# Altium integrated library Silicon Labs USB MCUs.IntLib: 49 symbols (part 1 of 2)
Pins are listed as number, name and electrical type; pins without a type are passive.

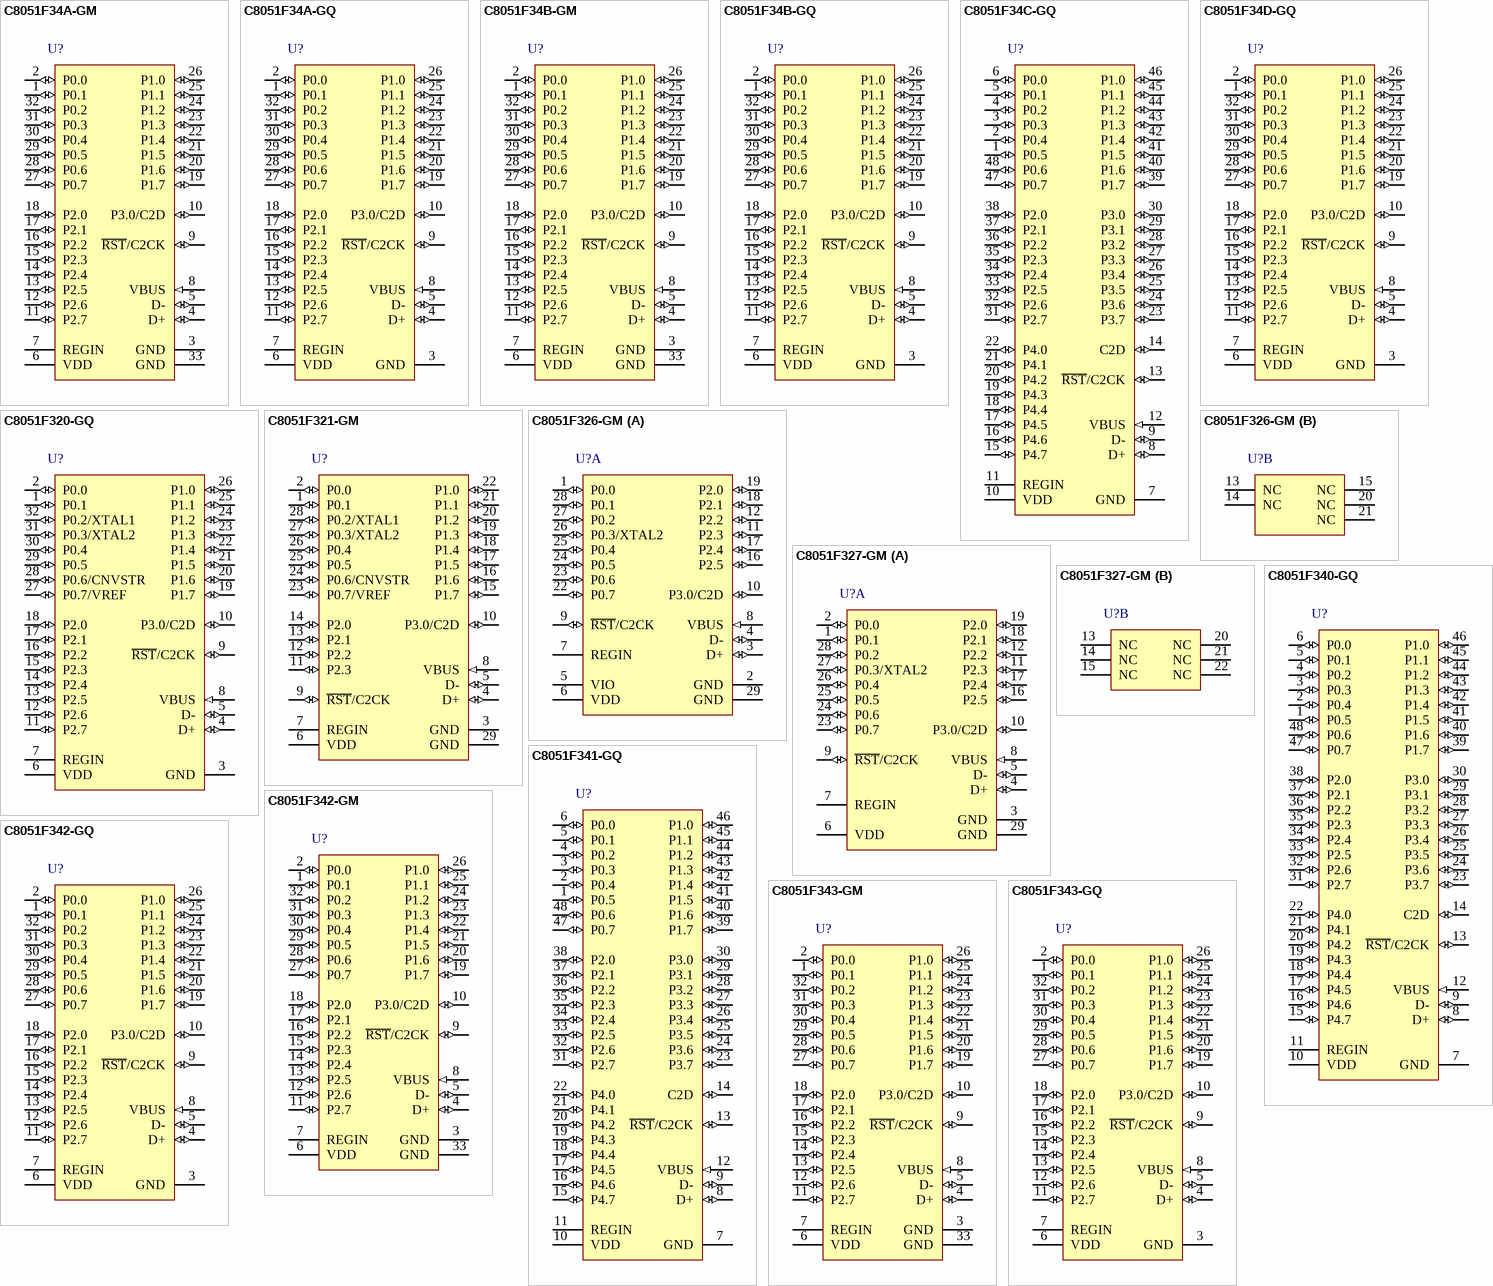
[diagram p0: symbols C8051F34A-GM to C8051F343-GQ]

## C8051F34A-GM
designator U?
Full Speed USB Flash MCU Family, 48 MHz, 4.25 kB RAM, 64 kB Flash, -40 to 85 degC, 32-pin QFN; Manufacturer: Silicon Labs; PartNumber: C8051F34A-GM; AEC-Q100: FALSE; Debug Interface: C2; Dig I/O Pins: 25; Flash: 64 kB; Internal Osc. Accuracy: +/-0.25%; MCU Core: 8051; MHz: 48; PCA Channels: 5; RAM: 4.25 KB; Temp Sensor: TRUE; Timers (16-bit): 4; Sub-Family: USB MCUs
footprint SLAB-QFN-32-3300x3300TP_N (QFN, 32-Leads, Body 5x5mm, Pitch 0.5mm, Thermal Pad 3.3x3.3mm, IPC Medium Density)
footprint SLAB-QFN-32-3300x3300TP_L (QFN, 32-Leads, Body 5x5mm, Pitch 0.5mm, Thermal Pad 3.3x3.3mm, IPC High Density)
footprint SLAB-QFN-32-3300x3300TP_M (QFN, 32-Leads, Body 5x5mm, Pitch 0.5mm, Thermal Pad 3.3x3.3mm, IPC Low Density)
pins: 1 P0.1 (io) "Port 0.1.", 2 P0.0 (io) "Port 0.0.", 3 GND (power) "Ground.", 4 D+ (io) "USB D+.", 5 D- (io) "USB D-", 6 VDD (power) "2.7-3.6 V Power Supply Voltage Input. 3.3 V Voltage Regulator Output.", 7 REGIN (power) "5 V Regulator Input. This pin is the input to the on-chip  voltage regulator.", 8 VBUS (in) "VBUS Sense Input. This pin should be connected to the VBUS signal of a USB network. A 5 V signal on this pin indicates a USB network connection.", 9 ~{RST}/C2CK (io), 10 P3.0/C2D (io), 11 P2.7 (io) "Port 2.7.", 12 P2.6 (io) "Port 2.6.", 13 P2.5 (io) "Port 2.5.", 14 P2.4 (io) "Port 2.4.", 15 P2.3 (io) "Port 2.3.", 16 P2.2 (io) "Port 2.2.", 17 P2.1 (io) "Port 2.1.", 18 P2.0 (io) "Port 2.0.", 19 P1.7 (io) "Port 1.7.", 20 P1.6 (io) "Port 1.6.", 21 P1.5 (io) "Port 1.5.", 22 P1.4 (io) "Port 1.4.", 23 P1.3 (io) "Port 1.3.", 24 P1.2 (io) "Port 1.2.", 25 P1.1 (io) "Port 1.1.", 26 P1.0 (io) "Port 1.0.", 27 P0.7 (io) "Port 0.7.", 28 P0.6 (io) "Port 0.6.", 29 P0.5 (io) "Port 0.5.", 30 P0.4 (io) "Port 0.4.", 31 P0.3 (io) "Port 0.3.", 32 P0.2 (io) "Port 0.2.", 33 GND (power)

## C8051F34A-GQ
designator U?
Full Speed USB Flash MCU Family, 48 MHz, 4.25 kB RAM, 64 kB Flash, -40 to 85 degC, 32-pin QFP; Manufacturer: Silicon Labs; PartNumber: C8051F34A-GQ; AEC-Q100: FALSE; Debug Interface: C2; Dig I/O Pins: 25; Flash: 64 kB; Internal Osc. Accuracy: +/-0.25%; MCU Core: 8051; MHz: 48; PCA Channels: 5; RAM: 4.25 KB; Temp Sensor: TRUE; Timers (16-bit): 4; Sub-Family: USB MCUs
footprint SLAB-LQFP-32_N (QFP, 32-Leads, Body 7x7mm, Pitch 0.8mm, IPC Medium Density)
footprint SLAB-LQFP-32_L (QFP, 32-Leads, Body 7x7mm, Pitch 0.8mm, IPC High Density)
footprint SLAB-LQFP-32_M (QFP, 32-Leads, Body 7x7mm, Pitch 0.8mm, IPC Low Density)
pins: 1 P0.1 (io) "Port 0.1", 2 P0.0 (io) "Port 0.0. See Section 15 for a complete description of Port 0", 3 GND (power) "Ground.", 4 D+ (io) "USB D+.", 5 D- (io) "USB D-.", 6 VDD (power) "2.7-3.6 V Power Supply Voltage Input. 3.3 V Voltage Regulator Output. See Section 8.", 7 REGIN (power) "5 V Regulator Input. This pin is the input to the on-chip voltage regulator.", 8 VBUS (in) "VBUS Sense Input. This pin should be connected to the VBUS signal of a USB network. A 5 V signal on this pin indicates a USB network connection.", 9 ~{RST}/C2CK (io), 10 P3.0/C2D (io), 11 P2.7 (io) "Port 2.7.", 12 P2.6 (io) "Port 2.6.", 13 P2.5 (io) "Port 2.5.", 14 P2.4 (io) "Port 2.4.", 15 P2.3 (io) "Port 2.3.", 16 P2.2 (io) "Port 2.2.", 17 P2.1 (io) "Port 2.1.", 18 P2.0 (io) "Port 2.0. See Section 15 for a complete description of Port 2.", 19 P1.7 (io) "Port 1.7.", 20 P1.6 (io) "Port 1.6.", 21 P1.5 (io) "Port 1.5.", 22 P1.4 (io) "Port 1.4.", 23 P1.3 (io) "Port 1.3.", 24 P1.2 (io) "Port 1.2.", 25 P1.1 (io) "Port 1.1.", 26 P1.0 (io) "Port 1.0. See Section 15 for a complete description of Port 3.", 27 P0.7 (io) "Port 0.7", 28 P0.6 (io) "Port 0.6", 29 P0.5 (io) "Port 0.5", 30 P0.4 (io) "Port 0.4", 31 P0.3 (io) "Port 0.3", 32 P0.2 (io) "Port 0.2"

## C8051F34B-GM
designator U?
Full Speed USB Flash MCU Family, 48 MHz, 2.25 kB RAM, 32 kB Flash, -40 to 85 degC, 32-pin QFN; Manufacturer: Silicon Labs; PartNumber: C8051F34B-GM; AEC-Q100: FALSE; Debug Interface: C2; Dig I/O Pins: 25; Flash: 32 kB; Internal Osc. Accuracy: +/-0.25%; MCU Core: 8051; MHz: 48; PCA Channels: 5; RAM: 2.25 KB; Temp Sensor: TRUE; Timers (16-bit): 4; Sub-Family: USB MCUs
footprint SLAB-QFN-32-3300x3300TP_N (QFN, 32-Leads, Body 5x5mm, Pitch 0.5mm, Thermal Pad 3.3x3.3mm, IPC Medium Density)
footprint SLAB-QFN-32-3300x3300TP_L (QFN, 32-Leads, Body 5x5mm, Pitch 0.5mm, Thermal Pad 3.3x3.3mm, IPC High Density)
footprint SLAB-QFN-32-3300x3300TP_M (QFN, 32-Leads, Body 5x5mm, Pitch 0.5mm, Thermal Pad 3.3x3.3mm, IPC Low Density)
pins: 1 P0.1 (io) "Port 0.1.", 2 P0.0 (io) "Port 0.0.", 3 GND (power) "Ground.", 4 D+ (io) "USB D+.", 5 D- (io) "USB D-", 6 VDD (power) "2.7-3.6 V Power Supply Voltage Input. 3.3 V Voltage Regulator Output.", 7 REGIN (power) "5 V Regulator Input. This pin is the input to the on-chip  voltage regulator.", 8 VBUS (in) "VBUS Sense Input. This pin should be connected to the VBUS signal of a USB network. A 5 V signal on this pin indicates a USB network connection.", 9 ~{RST}/C2CK (io), 10 P3.0/C2D (io), 11 P2.7 (io) "Port 2.7.", 12 P2.6 (io) "Port 2.6.", 13 P2.5 (io) "Port 2.5.", 14 P2.4 (io) "Port 2.4.", 15 P2.3 (io) "Port 2.3.", 16 P2.2 (io) "Port 2.2.", 17 P2.1 (io) "Port 2.1.", 18 P2.0 (io) "Port 2.0.", 19 P1.7 (io) "Port 1.7.", 20 P1.6 (io) "Port 1.6.", 21 P1.5 (io) "Port 1.5.", 22 P1.4 (io) "Port 1.4.", 23 P1.3 (io) "Port 1.3.", 24 P1.2 (io) "Port 1.2.", 25 P1.1 (io) "Port 1.1.", 26 P1.0 (io) "Port 1.0.", 27 P0.7 (io) "Port 0.7.", 28 P0.6 (io) "Port 0.6.", 29 P0.5 (io) "Port 0.5.", 30 P0.4 (io) "Port 0.4.", 31 P0.3 (io) "Port 0.3.", 32 P0.2 (io) "Port 0.2.", 33 GND (power)

## C8051F34B-GQ
designator U?
Full Speed USB Flash MCU Family, 48 MHz, 2.25 kB RAM, 32 kB Flash, -40 to 85 degC, 32-pin QFP; Manufacturer: Silicon Labs; PartNumber: C8051F34B-GQ; AEC-Q100: FALSE; Debug Interface: C2; Dig I/O Pins: 25; Flash: 32 kB; Internal Osc. Accuracy: +/-0.25%; MCU Core: 8051; MHz: 48; PCA Channels: 5; RAM: 2.25 KB; Temp Sensor: TRUE; Timers (16-bit): 4; Sub-Family: USB MCUs
footprint SLAB-LQFP-32_N (QFP, 32-Leads, Body 7x7mm, Pitch 0.8mm, IPC Medium Density)
footprint SLAB-LQFP-32_L (QFP, 32-Leads, Body 7x7mm, Pitch 0.8mm, IPC High Density)
footprint SLAB-LQFP-32_M (QFP, 32-Leads, Body 7x7mm, Pitch 0.8mm, IPC Low Density)
pins: 1 P0.1 (io) "Port 0.1", 2 P0.0 (io) "Port 0.0. See Section 15 for a complete description of Port 0", 3 GND (power) "Ground.", 4 D+ (io) "USB D+.", 5 D- (io) "USB D-.", 6 VDD (power) "2.7-3.6 V Power Supply Voltage Input. 3.3 V Voltage Regulator Output. See Section 8.", 7 REGIN (power) "5 V Regulator Input. This pin is the input to the on-chip voltage regulator.", 8 VBUS (in) "VBUS Sense Input. This pin should be connected to the VBUS signal of a USB network. A 5 V signal on this pin indicates a USB network connection.", 9 ~{RST}/C2CK (io), 10 P3.0/C2D (io), 11 P2.7 (io) "Port 2.7.", 12 P2.6 (io) "Port 2.6.", 13 P2.5 (io) "Port 2.5.", 14 P2.4 (io) "Port 2.4.", 15 P2.3 (io) "Port 2.3.", 16 P2.2 (io) "Port 2.2.", 17 P2.1 (io) "Port 2.1.", 18 P2.0 (io) "Port 2.0. See Section 15 for a complete description of Port 2.", 19 P1.7 (io) "Port 1.7.", 20 P1.6 (io) "Port 1.6.", 21 P1.5 (io) "Port 1.5.", 22 P1.4 (io) "Port 1.4.", 23 P1.3 (io) "Port 1.3.", 24 P1.2 (io) "Port 1.2.", 25 P1.1 (io) "Port 1.1.", 26 P1.0 (io) "Port 1.0. See Section 15 for a complete description of Port 3.", 27 P0.7 (io) "Port 0.7", 28 P0.6 (io) "Port 0.6", 29 P0.5 (io) "Port 0.5", 30 P0.4 (io) "Port 0.4", 31 P0.3 (io) "Port 0.3", 32 P0.2 (io) "Port 0.2"

## C8051F34C-GQ
designator U?
Full Speed USB Flash MCU Family, 48 MHz, 4.25 kB RAM, 64 kB Flash, -40 to 85 degC, 48-pin QFP; Manufacturer: Silicon Labs; PartNumber: C8051F34C-GQ; AEC-Q100: FALSE; Debug Interface: C2; Dig I/O Pins: 40; Flash: 64 kB; Internal Osc. Accuracy: +/-0.25%; MCU Core: 8051; MHz: 48; PCA Channels: 5; RAM: 4.25 KB; Temp Sensor: TRUE; Timers (16-bit): 4; Sub-Family: USB MCUs
footprint SLAB-TQFP-48_N (QFP, 48-Leads, Body 7x7mm, Pitch 0.5mm, IPC Medium Density)
footprint SLAB-TQFP-48_L (QFP, 48-Leads, Body 7x7mm, Pitch 0.5mm, IPC High Density)
footprint SLAB-TQFP-48_M (QFP, 48-Leads, Body 7x7mm, Pitch 0.5mm, IPC Low Density)
pins: 1 P0.5 (io) "Port 0.5.", 2 P0.4 (io) "Port 0.4.", 3 P0.3 (io) "Port 0.3.", 4 P0.2 (io) "Port 0.2.", 5 P0.1 (io) "Port 0.1", 6 P0.0 (io) "Port 0.0.", 7 GND (power) "Ground.", 8 D+ (io) "USB D+.", 9 D- (io) "USB D-.", 10 VDD (power) "2.7-3.6 V Power Supply Voltage Input. 3.3 V Voltage Regulator Output.", 11 REGIN (power) "5 V Regulator Input. This pin is the input to the on-chip voltage regulator.", 12 VBUS (in) "VBUS Sense Input. This pin should be connected to the VBUS signal of a USB network. A 5 V signal on this pin indicates a USB network connection.", 13 ~{RST}/C2CK (io), 14 C2D (io) "Bi-directional data signal for the C2 Debug Interface.", 15 P4.7 (io) "Port 4.7.", 16 P4.6 (io) "Port 4.6.", 17 P4.5 (io) "Port 4.5.", 18 P4.4 (io) "Port 4.4.", 19 P4.3 (io) "Port 4.3.", 20 P4.2 (io) "Port 4.2.", 21 P4.1 (io) "Port 4.1.", 22 P4.0 (io) "Port 4.0.", 23 P3.7 (io) "Port 3.7.", 24 P3.6 (io) "Port 3.6.", 25 P3.5 (io) "Port 3.5.", 26 P3.4 (io) "Port 3.4.", 27 P3.3 (io) "Port 3.3.", 28 P3.2 (io) "Port 3.2.", 29 P3.1 (io) "Port 3.1.", 30 P3.0 (io) "Port 3.0.", 31 P2.7 (io) "Port 2.7.", 32 P2.6 (io) "Port 2.6.", 33 P2.5 (io) "Port 2.5.", 34 P2.4 (io) "Port 2.4.", 35 P2.3 (io) "Port 2.3.", 36 P2.2 (io) "Port 2.2.", 37 P2.1 (io) "Port 2.1.", 38 P2.0 (io) "Port 2.0.", 39 P1.7 (io) "Port 1.7.", 40 P1.6 (io) "Port 1.6.", 41 P1.5 (io) "Port 1.5.", 42 P1.4 (io) "Port 1.4.", 43 P1.3 (io) "Port 1.3.", 44 P1.2 (io) "Port 1.2.", 45 P1.1 (io) "Port 1.1.", 46 P1.0 (io) "Port 1.0.", 47 P0.7 (io) "Port 0.7.", 48 P0.6 (io) "Port 0.6."

## C8051F34D-GQ
designator U?
Full Speed USB Flash MCU Family, 48 MHz, 4.25 kB RAM, 64 kB Flash, -40 to 85 degC, 32-pin QFP; Manufacturer: Silicon Labs; PartNumber: C8051F34D-GQ; AEC-Q100: FALSE; Debug Interface: C2; Dig I/O Pins: 25; Flash: 64 kB; Internal Osc. Accuracy: +/-0.25%; MCU Core: 8051; MHz: 48; PCA Channels: 5; RAM: 4.25 KB; Temp Sensor: TRUE; Timers (16-bit): 4; Sub-Family: USB MCUs
footprint SLAB-LQFP-32_N (QFP, 32-Leads, Body 7x7mm, Pitch 0.8mm, IPC Medium Density)
footprint SLAB-LQFP-32_L (QFP, 32-Leads, Body 7x7mm, Pitch 0.8mm, IPC High Density)
footprint SLAB-LQFP-32_M (QFP, 32-Leads, Body 7x7mm, Pitch 0.8mm, IPC Low Density)
pins: 1 P0.1 (io) "Port 0.1", 2 P0.0 (io) "Port 0.0. See Section 15 for a complete description of Port 0", 3 GND (power) "Ground.", 4 D+ (io) "USB D+.", 5 D- (io) "USB D-.", 6 VDD (power) "2.7-3.6 V Power Supply Voltage Input. 3.3 V Voltage Regulator Output. See Section 8.", 7 REGIN (power) "5 V Regulator Input. This pin is the input to the on-chip voltage regulator.", 8 VBUS (in) "VBUS Sense Input. This pin should be connected to the VBUS signal of a USB network. A 5 V signal on this pin indicates a USB network connection.", 9 ~{RST}/C2CK (io), 10 P3.0/C2D (io), 11 P2.7 (io) "Port 2.7.", 12 P2.6 (io) "Port 2.6.", 13 P2.5 (io) "Port 2.5.", 14 P2.4 (io) "Port 2.4.", 15 P2.3 (io) "Port 2.3.", 16 P2.2 (io) "Port 2.2.", 17 P2.1 (io) "Port 2.1.", 18 P2.0 (io) "Port 2.0. See Section 15 for a complete description of Port 2.", 19 P1.7 (io) "Port 1.7.", 20 P1.6 (io) "Port 1.6.", 21 P1.5 (io) "Port 1.5.", 22 P1.4 (io) "Port 1.4.", 23 P1.3 (io) "Port 1.3.", 24 P1.2 (io) "Port 1.2.", 25 P1.1 (io) "Port 1.1.", 26 P1.0 (io) "Port 1.0. See Section 15 for a complete description of Port 3.", 27 P0.7 (io) "Port 0.7", 28 P0.6 (io) "Port 0.6", 29 P0.5 (io) "Port 0.5", 30 P0.4 (io) "Port 0.4", 31 P0.3 (io) "Port 0.3", 32 P0.2 (io) "Port 0.2"

## C8051F320-GQ
designator U?
Full Speed USB, ISP Flash MCU Family, 25 MHz, 2.25 kB RAM, 16 kB Flash, -40 to 85 degC, 32-pin QFP; Manufacturer: Silicon Labs; PartNumber: C8051F320-GQ; ADC 1: 10-bit, 17-ch., 200 ksps; AEC-Q100: FALSE; Comparators: 2; Debug Interface: C2; Dig I/O Pins: 25; Flash: 16 kB; Internal Osc. Accuracy: +/-0.25%; MCU Core: 8051; PCA Channels: 5; RAM: 2.25 KB; Temp Sensor: TRUE; Timers (16-bit): 4; Sub-Family: USB MCUs
footprint SLAB-LQFP-32_N (QFP, 32-Leads, Body 7x7mm, Pitch 0.8mm, IPC Medium Density)
footprint SLAB-LQFP-32_L (QFP, 32-Leads, Body 7x7mm, Pitch 0.8mm, IPC High Density)
footprint SLAB-LQFP-32_M (QFP, 32-Leads, Body 7x7mm, Pitch 0.8mm, IPC Low Density)
pins: 1 P0.1 (io) "Port 0.1.", 2 P0.0 (io) "Port 0.0. See Section 14 for a complete description of Port 0.", 3 GND (power) "Ground.", 4 D+ (io) "USB D+.", 5 D- (io) "USB D-", 6 VDD (power) "2.7-3.6 V Power Supply Voltage Input. 3.3 V Voltage Regulator Output. See Section 8.", 7 REGIN (power) "5 V Regulator Input. This pin is the input to the on-chip  voltage regulator.", 8 VBUS (in) "VBUS Sense Input. This pin should be connected to the VBUS signal of a USB network. A 5 V signal on this pin indicates a USB network connection.", 9 ~{RST}/C2CK (io), 10 P3.0/C2D (io), 11 P2.7 (io) "Port 2.7.", 12 P2.6 (io) "Port 2.6.", 13 P2.5 (io) "Port 2.5.", 14 P2.4 (io) "Port 2.4.", 15 P2.3 (io) "Port 2.3.", 16 P2.2 (io) "Port 2.2.", 17 P2.1 (io) "Port 2.1.", 18 P2.0 (io) "Port 2.0. See Section 20 for a complete description of Port 2.", 19 P1.7 (io) "Port 1.7.", 20 P1.6 (io) "Port 1.6.", 21 P1.5 (io) "Port 1.5.", 22 P1.4 (io) "Port 1.4.", 23 P1.3 (io) "Port 1.3.", 24 P1.2 (io) "Port 1.2.", 25 P1.1 (io) "Port 1.1.", 26 P1.0 (io) "Port 1.0. See Section 20 for a complete description of Port 1.", 27 P0.7/VREF (io), 28 P0.6/CNVSTR (io), 29 P0.5 (io) "Port 0.5.", 30 P0.4 (io) "Port 0.4.", 31 P0.3/XTAL2 (io), 32 P0.2/XTAL1 (io)

## C8051F321-GM
designator U?
Full Speed USB, ISP Flash MCU Family, 25 MHz, 2.25 kB RAM, 16 kB Flash, -40 to 85 degC, 28-pin QFN; Manufacturer: Silicon Labs; PartNumber: C8051F321-GM; ADC 1: 10-bit, 13-ch., 200 ksps; AEC-Q100: FALSE; Comparators: 2; Debug Interface: C2; Dig I/O Pins: 21; Flash: 16 kB; Internal Osc. Accuracy: +/-0.25%; MCU Core: 8051; MHz: 25; PCA Channels: 5; RAM: 2.25 KB; Temp Sensor: TRUE; Timers (16-bit): 4; Sub-Family: USB MCUs
footprint SLAB-QFN-28-3125x3125TP_N (QFN, 28-Leads, Body 5x5mm, Pitch 0.5mm, Thermal Pad 3.13x3.13mm, IPC Medium Density)
footprint SLAB-QFN-28-3125x3125TP_L (QFN, 28-Leads, Body 5x5mm, Pitch 0.5mm, Thermal Pad 3.13x3.13mm, IPC High Density)
footprint SLAB-QFN-28-3125x3125TP_M (QFN, 28-Leads, Body 5x5mm, Pitch 0.5mm, Thermal Pad 3.13x3.13mm, IPC Low Density)
pins: 1 P0.1 (io) "Port 0.1.", 2 P0.0 (io) "Port 0.0. See Section 14 for a complete description of Port 0.", 3 GND (power) "Ground.", 4 D+ (io) "USB D+.", 5 D- (io) "USB D-", 6 VDD (power) "2.7-3.6 V Power Supply Voltage Input.3.3 V Voltage Regulator Output. See Section 8.", 7 REGIN (power) "5 V Regulator Input. This pin is the input to the on-chip  voltage regulator.", 8 VBUS (in) "VBUS Sense Input. This pin should be connected to the VBUS signal of a USB network. A 5 V signal on this pin indicates a USB network connection.", 9 ~{RST}/C2CK (io), 10 P3.0/C2D (io), 11 P2.3 (io) "Port 2.3.", 12 P2.2 (io) "Port 2.2.", 13 P2.1 (io) "Port 2.1.", 14 P2.0 (io) "Port 2.0. See Section 14 for a complete description of Port 2.", 15 P1.7 (io) "Port 1.7.", 16 P1.6 (io) "Port 1.6.", 17 P1.5 (io) "Port 1.5.", 18 P1.4 (io) "Port 1.4.", 19 P1.3 (io) "Port 1.3.", 20 P1.2 (io) "Port 1.2.", 21 P1.1 (io) "Port 1.1.", 22 P1.0 (io) "Port 1.0. See Section 14 for a complete description of Port 1.", 23 P0.7/VREF (io), 24 P0.6/CNVSTR (io), 25 P0.5 (io) "Port 0.5.", 26 P0.4 (io) "Port 0.4", 27 P0.3/XTAL2 (io), 28 P0.2/XTAL1 (io), 29 GND (power)

## C8051F326-GM
designator U?
Full Speed USB, Flash MCU Family, 25 MHz, 1.5 kB RAM, 16 kB Flash, -40 to 85 degC, 28-pin QFN; Manufacturer: Silicon Labs; PartNumber: C8051F326-GM; AEC-Q100: FALSE; Debug Interface: C2; Dig I/O Pins: 15; Flash: 16 kB; MCU Core: 8051; MHz: 25; PCA Channels: 5; RAM: 1.5 kB; Temp Sensor: TRUE; Timers (16-bit): 2; Sub-Family: USB MCUs
footprint SLAB-QFN-28-3125x3125TP_N (QFN, 28-Leads, Body 5x5mm, Pitch 0.5mm, Thermal Pad 3.13x3.13mm, IPC Medium Density)
footprint SLAB-QFN-28-3125x3125TP_L (QFN, 28-Leads, Body 5x5mm, Pitch 0.5mm, Thermal Pad 3.13x3.13mm, IPC High Density)
footprint SLAB-QFN-28-3125x3125TP_M (QFN, 28-Leads, Body 5x5mm, Pitch 0.5mm, Thermal Pad 3.13x3.13mm, IPC Low Density)
part A pins: 1 P0.0 (io) "Port 0.0. See Section 11 for a complete description.", 2 GND (power) "Ground.", 3 D+ (io) "USB D+.", 4 D- (io) "USB D-", 5 VIO (power) "V I/O Supply Voltage Input. The voltage at this pin must be  less than or equal to the Core Supply Voltage (VDD) for the  'F326. On the 'F327, this pin is internally connected to VDD.", 6 VDD (power) "2.7-3.6 V Core Supply Voltage Input. 3.3 V Voltage Regulator Output. See Section 5.", 7 REGIN (power) "5 V Regulator Input. This pin is the input to the on-chip  voltage regulator.", 8 VBUS (in) "VBUS Sense Input. This pin should be connected to the VBUS signal of a USB network. A 5 V signal on this pin indicates a USB network connection.", 9 ~{RST}/C2CK (io), 10 P3.0/C2D (io), 11 P2.3 (io) "Port 2.3.See Section 11 for a complete description.", 12 P2.2 (io) "Port 2.2.See Section 11 for a complete description.", 16 P2.5 (io) "Port 2.5. See Section 11 for a complete description.", 17 P2.4 (io) "Port 2.4. See Section 11 for a complete description.", 18 P2.1 (io) "Port 2.1. See Section 11 for a complete description.", 19 P2.0 (io) "Port 2.0. See Section 11 for a complete description.", 22 P0.7 (io) "Port 0.7. See Section 11 for a complete description.", 23 P0.6 (io) "Port 0.6. See Section 11 for a complete description.", 24 P0.5 (io) "Port 0.5. See Section 11 for a complete description.", 25 P0.4 (io) "Port 0.4. See Section 11 for a complete description.", 26 P0.3/XTAL2 (io), 27 P0.2 (io) "Port 0.2. See Section 11 for a complete description.", 28 P0.1 (io) "Port 0.1. See Section 11 for a complete description.", 29 GND (power)
part B pins: 13 NC, 14 NC, 15 NC, 20 NC, 21 NC

## C8051F327-GM
designator U?
Full Speed USB, Flash MCU Family, 25 MHz, 1.5 kB RAM, 16 kB Flash, -40 to 85 degC, 28-pin QFN; Manufacturer: Silicon Labs; PartNumber: C8051F327-GM; AEC-Q100: FALSE; Debug Interface: C2; Dig I/O Pins: 15; Flash: 16 kB; MCU Core: 8051; MHz: 25; PCA Channels: 5; RAM: 1.5 kB; Temp Sensor: TRUE; Timers (16-bit): 2; Sub-Family: USB MCUs
footprint SLAB-QFN-28-3125x3125TP_N (QFN, 28-Leads, Body 5x5mm, Pitch 0.5mm, Thermal Pad 3.13x3.13mm, IPC Medium Density)
footprint SLAB-QFN-28-3125x3125TP_L (QFN, 28-Leads, Body 5x5mm, Pitch 0.5mm, Thermal Pad 3.13x3.13mm, IPC High Density)
footprint SLAB-QFN-28-3125x3125TP_M (QFN, 28-Leads, Body 5x5mm, Pitch 0.5mm, Thermal Pad 3.13x3.13mm, IPC Low Density)
part A pins: 1 P0.1 (io) "Port 0.1. See Section 11 for a complete description.", 2 P0.0 (io) "Port 0.0. See Section 11 for a complete description.", 3 GND (power) "Ground.", 4 D+ (io) "USB D+.", 5 D- (io) "USB D-", 6 VDD (power) "2.7-3.6 V Core Supply Voltage Input. 3.3 V Voltage Regulator Output. See Section 5.", 7 REGIN (power) "5 V Regulator Input. This pin is the input to the on-chip  voltage regulator.", 8 VBUS (in) "VBUS Sense Input. This pin should be connected to the VBUS signal of a USB network. A 5 V signal on this pin indicates a USB network connection.", 9 ~{RST}/C2CK (io), 10 P3.0/C2D (io), 11 P2.3 (io) "Port 2.3.See Section 11 for a complete description.", 12 P2.2 (io) "Port 2.2.See Section 11 for a complete description.", 16 P2.5 (io) "Port 2.5. See Section 11 for a complete description.", 17 P2.4 (io) "Port 2.4. See Section 11 for a complete description.", 18 P2.1 (io) "Port 2.1. See Section 11 for a complete description.", 19 P2.0 (io) "Port 2.0. See Section 11 for a complete description.", 23 P0.7 (io) "Port 0.7. See Section 11 for a complete description.", 24 P0.6 (io) "Port 0.6. See Section 11 for a complete description.", 25 P0.5 (io) "Port 0.5. See Section 11 for a complete description.", 26 P0.4 (io) "Port 0.4. See Section 11 for a complete description.", 27 P0.3/XTAL2 (io), 28 P0.2 (io) "Port 0.2. See Section 11 for a complete description.", 29 GND (power)
part B pins: 13 NC, 14 NC, 15 NC, 20 NC, 21 NC, 22 NC

## C8051F340-GQ
designator U?
Full Speed USB Flash MCU Family, 48 MHz, 4.25 kB RAM, 64 kB Flash, -40 to 85 degC, 48-pin QFP; Manufacturer: Silicon Labs; PartNumber: C8051F340-GQ; ADC 1: 10-bit, 20-ch., 200 ksps; AEC-Q100: FALSE; Comparators: 2; Debug Interface: C2; Dig I/O Pins: 40; Flash: 64 kB; Internal Osc. Accuracy: +/-0.25%; MCU Core: 8051; MHz: 48; PCA Channels: 5; RAM: 4.25 kB; Temp Sensor: TRUE; Timers (16-bit): 4; Sub-Family: USB MCUs
footprint SLAB-TQFP-48_N (QFP, 48-Leads, Body 7x7mm, Pitch 0.5mm, IPC Medium Density)
footprint SLAB-TQFP-48_L (QFP, 48-Leads, Body 7x7mm, Pitch 0.5mm, IPC High Density)
footprint SLAB-TQFP-48_M (QFP, 48-Leads, Body 7x7mm, Pitch 0.5mm, IPC Low Density)
pins: 1 P0.5 (io) "Port 0.5.", 2 P0.4 (io) "Port 0.4.", 3 P0.3 (io) "Port 0.3.", 4 P0.2 (io) "Port 0.2.", 5 P0.1 (io) "Port 0.1", 6 P0.0 (io) "Port 0.0.", 7 GND (power) "Ground.", 8 D+ (io) "USB D+.", 9 D- (io) "USB D-.", 10 VDD (power) "2.7-3.6 V Power Supply Voltage Input. 3.3 V Voltage Regulator Output.", 11 REGIN (power) "5 V Regulator Input. This pin is the input to the on-chip voltage regulator.", 12 VBUS (in) "VBUS Sense Input. This pin should be connected to the VBUS signal of a USB network. A 5 V signal on this pin indicates a USB network connection.", 13 ~{RST}/C2CK (io), 14 C2D (io) "Bi-directional data signal for the C2 Debug Interface.", 15 P4.7 (io) "Port 4.7.", 16 P4.6 (io) "Port 4.6.", 17 P4.5 (io) "Port 4.5.", 18 P4.4 (io) "Port 4.4.", 19 P4.3 (io) "Port 4.3.", 20 P4.2 (io) "Port 4.2.", 21 P4.1 (io) "Port 4.1.", 22 P4.0 (io) "Port 4.0.", 23 P3.7 (io) "Port 3.7.", 24 P3.6 (io) "Port 3.6.", 25 P3.5 (io) "Port 3.5.", 26 P3.4 (io) "Port 3.4.", 27 P3.3 (io) "Port 3.3.", 28 P3.2 (io) "Port 3.2.", 29 P3.1 (io) "Port 3.1.", 30 P3.0 (io) "Port 3.0.", 31 P2.7 (io) "Port 2.7.", 32 P2.6 (io) "Port 2.6.", 33 P2.5 (io) "Port 2.5.", 34 P2.4 (io) "Port 2.4.", 35 P2.3 (io) "Port 2.3.", 36 P2.2 (io) "Port 2.2.", 37 P2.1 (io) "Port 2.1.", 38 P2.0 (io) "Port 2.0.", 39 P1.7 (io) "Port 1.7.", 40 P1.6 (io) "Port 1.6.", 41 P1.5 (io) "Port 1.5.", 42 P1.4 (io) "Port 1.4.", 43 P1.3 (io) "Port 1.3.", 44 P1.2 (io) "Port 1.2.", 45 P1.1 (io) "Port 1.1.", 46 P1.0 (io) "Port 1.0.", 47 P0.7 (io) "Port 0.7.", 48 P0.6 (io) "Port 0.6."

## C8051F341-GQ
designator U?
Full Speed USB Flash MCU Family, 48 MHz, 2.25 kB RAM, 32 kB Flash, -40 to 85 degC, 48-pin QFP; Manufacturer: Silicon Labs; PartNumber: C8051F341-GQ; ADC 1: 10-bit, 20-ch., 200 ksps; AEC-Q100: FALSE; Comparators: 2; Debug Interface: C2; Dig I/O Pins: 40; Flash: 32 kB; Internal Osc. Accuracy: +/-0.25%; MCU Core: 8051; MHz: 48; PCA Channels: 5; RAM: 2.25 kB; Temp Sensor: TRUE; Timers (16-bit): 4; Sub-Family: USB MCUs
footprint SLAB-TQFP-48_N (QFP, 48-Leads, Body 7x7mm, Pitch 0.5mm, IPC Medium Density)
footprint SLAB-TQFP-48_L (QFP, 48-Leads, Body 7x7mm, Pitch 0.5mm, IPC High Density)
footprint SLAB-TQFP-48_M (QFP, 48-Leads, Body 7x7mm, Pitch 0.5mm, IPC Low Density)
pins: 1 P0.5 (io) "Port 0.5.", 2 P0.4 (io) "Port 0.4.", 3 P0.3 (io) "Port 0.3.", 4 P0.2 (io) "Port 0.2.", 5 P0.1 (io) "Port 0.1", 6 P0.0 (io) "Port 0.0.", 7 GND (power) "Ground.", 8 D+ (io) "USB D+.", 9 D- (io) "USB D-.", 10 VDD (power) "2.7-3.6 V Power Supply Voltage Input. 3.3 V Voltage Regulator Output.", 11 REGIN (power) "5 V Regulator Input. This pin is the input to the on-chip voltage regulator.", 12 VBUS (in) "VBUS Sense Input. This pin should be connected to the VBUS signal of a USB network. A 5 V signal on this pin indicates a USB network connection.", 13 ~{RST}/C2CK (io), 14 C2D (io) "Bi-directional data signal for the C2 Debug Interface.", 15 P4.7 (io) "Port 4.7.", 16 P4.6 (io) "Port 4.6.", 17 P4.5 (io) "Port 4.5.", 18 P4.4 (io) "Port 4.4.", 19 P4.3 (io) "Port 4.3.", 20 P4.2 (io) "Port 4.2.", 21 P4.1 (io) "Port 4.1.", 22 P4.0 (io) "Port 4.0.", 23 P3.7 (io) "Port 3.7.", 24 P3.6 (io) "Port 3.6.", 25 P3.5 (io) "Port 3.5.", 26 P3.4 (io) "Port 3.4.", 27 P3.3 (io) "Port 3.3.", 28 P3.2 (io) "Port 3.2.", 29 P3.1 (io) "Port 3.1.", 30 P3.0 (io) "Port 3.0.", 31 P2.7 (io) "Port 2.7.", 32 P2.6 (io) "Port 2.6.", 33 P2.5 (io) "Port 2.5.", 34 P2.4 (io) "Port 2.4.", 35 P2.3 (io) "Port 2.3.", 36 P2.2 (io) "Port 2.2.", 37 P2.1 (io) "Port 2.1.", 38 P2.0 (io) "Port 2.0.", 39 P1.7 (io) "Port 1.7.", 40 P1.6 (io) "Port 1.6.", 41 P1.5 (io) "Port 1.5.", 42 P1.4 (io) "Port 1.4.", 43 P1.3 (io) "Port 1.3.", 44 P1.2 (io) "Port 1.2.", 45 P1.1 (io) "Port 1.1.", 46 P1.0 (io) "Port 1.0.", 47 P0.7 (io) "Port 0.7.", 48 P0.6 (io) "Port 0.6."

## C8051F342-GM
designator U?
Full Speed USB Flash MCU Family, 48 MHz, 4.25 kB RAM, 64 kB Flash, -40 to 85 degC, 32-pin QFN; Manufacturer: Silicon Labs; PartNumber: C8051F342-GM; ADC 1: 10-bit, 21-ch., 200 ksps; AEC-Q100: FALSE; Comparators: 2; Debug Interface: C2; Dig I/O Pins: 25; Flash: 64 kB; Internal Osc. Accuracy: +/-0.25%; MCU Core: 8051; MHz: 48; PCA Channels: 5; RAM: 4.25 kB; Temp Sensor: TRUE; Timers (16-bit): 4; Sub-Family: USB MCUs
footprint SLAB-QFN-32-3300x3300TP_N (QFN, 32-Leads, Body 5x5mm, Pitch 0.5mm, Thermal Pad 3.3x3.3mm, IPC Medium Density)
footprint SLAB-QFN-32-3300x3300TP_L (QFN, 32-Leads, Body 5x5mm, Pitch 0.5mm, Thermal Pad 3.3x3.3mm, IPC High Density)
footprint SLAB-QFN-32-3300x3300TP_M (QFN, 32-Leads, Body 5x5mm, Pitch 0.5mm, Thermal Pad 3.3x3.3mm, IPC Low Density)
pins: 1 P0.1 (io) "Port 0.1.", 2 P0.0 (io) "Port 0.0.", 3 GND (power) "Ground.", 4 D+ (io) "USB D+.", 5 D- (io) "USB D-", 6 VDD (power) "2.7-3.6 V Power Supply Voltage Input. 3.3 V Voltage Regulator Output.", 7 REGIN (power) "5 V Regulator Input. This pin is the input to the on-chip  voltage regulator.", 8 VBUS (in) "VBUS Sense Input. This pin should be connected to the VBUS signal of a USB network. A 5 V signal on this pin indicates a USB network connection.", 9 ~{RST}/C2CK (io), 10 P3.0/C2D (io), 11 P2.7 (io) "Port 2.7.", 12 P2.6 (io) "Port 2.6.", 13 P2.5 (io) "Port 2.5.", 14 P2.4 (io) "Port 2.4.", 15 P2.3 (io) "Port 2.3.", 16 P2.2 (io) "Port 2.2.", 17 P2.1 (io) "Port 2.1.", 18 P2.0 (io) "Port 2.0.", 19 P1.7 (io) "Port 1.7.", 20 P1.6 (io) "Port 1.6.", 21 P1.5 (io) "Port 1.5.", 22 P1.4 (io) "Port 1.4.", 23 P1.3 (io) "Port 1.3.", 24 P1.2 (io) "Port 1.2.", 25 P1.1 (io) "Port 1.1.", 26 P1.0 (io) "Port 1.0.", 27 P0.7 (io) "Port 0.7.", 28 P0.6 (io) "Port 0.6.", 29 P0.5 (io) "Port 0.5.", 30 P0.4 (io) "Port 0.4.", 31 P0.3 (io) "Port 0.3.", 32 P0.2 (io) "Port 0.2.", 33 GND (power)

## C8051F342-GQ
designator U?
Full Speed USB Flash MCU Family, 48 MHz, 4.25 kB RAM, 64 kB Flash, -40 to 85 degC, 32-pin QFP; Manufacturer: Silicon Labs; PartNumber: C8051F342-GQ; ADC 1: 10-bit, 21-ch., 200 ksps; AEC-Q100: FALSE; Comparators: 2; Debug Interface: C2; Dig I/O Pins: 25; Flash: 64 kB; Internal Osc. Accuracy: +/-0.25%; MCU Core: 8051; MHz: 48; PCA Channels: 5; RAM: 4.25 kB; Temp Sensor: TRUE; Timers (16-bit): 4; Sub-Family: USB MCUs
footprint SLAB-LQFP-32_N (QFP, 32-Leads, Body 7x7mm, Pitch 0.8mm, IPC Medium Density)
footprint SLAB-LQFP-32_L (QFP, 32-Leads, Body 7x7mm, Pitch 0.8mm, IPC High Density)
footprint SLAB-LQFP-32_M (QFP, 32-Leads, Body 7x7mm, Pitch 0.8mm, IPC Low Density)
pins: 1 P0.1 (io) "Port 0.1", 2 P0.0 (io) "Port 0.0. See Section 15 for a complete description of Port 0", 3 GND (power) "Ground.", 4 D+ (io) "USB D+.", 5 D- (io) "USB D-.", 6 VDD (power) "2.7-3.6 V Power Supply Voltage Input. 3.3 V Voltage Regulator Output. See Section 8.", 7 REGIN (power) "5 V Regulator Input. This pin is the input to the on-chip voltage regulator.", 8 VBUS (in) "VBUS Sense Input. This pin should be connected to the VBUS signal of a USB network. A 5 V signal on this pin indicates a USB network connection.", 9 ~{RST}/C2CK (io), 10 P3.0/C2D (io), 11 P2.7 (io) "Port 2.7.", 12 P2.6 (io) "Port 2.6.", 13 P2.5 (io) "Port 2.5.", 14 P2.4 (io) "Port 2.4.", 15 P2.3 (io) "Port 2.3.", 16 P2.2 (io) "Port 2.2.", 17 P2.1 (io) "Port 2.1.", 18 P2.0 (io) "Port 2.0. See Section 15 for a complete description of Port 2.", 19 P1.7 (io) "Port 1.7.", 20 P1.6 (io) "Port 1.6.", 21 P1.5 (io) "Port 1.5.", 22 P1.4 (io) "Port 1.4.", 23 P1.3 (io) "Port 1.3.", 24 P1.2 (io) "Port 1.2.", 25 P1.1 (io) "Port 1.1.", 26 P1.0 (io) "Port 1.0. See Section 15 for a complete description of Port 3.", 27 P0.7 (io) "Port 0.7", 28 P0.6 (io) "Port 0.6", 29 P0.5 (io) "Port 0.5", 30 P0.4 (io) "Port 0.4", 31 P0.3 (io) "Port 0.3", 32 P0.2 (io) "Port 0.2"

## C8051F343-GM
designator U?
Full Speed USB Flash MCU Family, 48 MHz, 2.25 kB RAM, 32 kB Flash, -40 to 85 degC, 32-pin QFN; Manufacturer: Silicon Labs; PartNumber: C8051F343-GM; ADC 1: 10-bit, 21-ch., 200 ksps; AEC-Q100: FALSE; Comparators: 2; Debug Interface: C2; Dig I/O Pins: 25; Flash: 32 kB; Internal Osc. Accuracy: +/-0.25%; MCU Core: 8051; MHz: 48; PCA Channels: 5; RAM: 2.25 kB; Temp Sensor: TRUE; Timers (16-bit): 4; Sub-Family: USB MCUs
footprint SLAB-QFN-32-3300x3300TP_N (QFN, 32-Leads, Body 5x5mm, Pitch 0.5mm, Thermal Pad 3.3x3.3mm, IPC Medium Density)
footprint SLAB-QFN-32-3300x3300TP_L (QFN, 32-Leads, Body 5x5mm, Pitch 0.5mm, Thermal Pad 3.3x3.3mm, IPC High Density)
footprint SLAB-QFN-32-3300x3300TP_M (QFN, 32-Leads, Body 5x5mm, Pitch 0.5mm, Thermal Pad 3.3x3.3mm, IPC Low Density)
pins: 1 P0.1 (io) "Port 0.1.", 2 P0.0 (io) "Port 0.0.", 3 GND (power) "Ground.", 4 D+ (io) "USB D+.", 5 D- (io) "USB D-", 6 VDD (power) "2.7-3.6 V Power Supply Voltage Input. 3.3 V Voltage Regulator Output.", 7 REGIN (power) "5 V Regulator Input. This pin is the input to the on-chip  voltage regulator.", 8 VBUS (in) "VBUS Sense Input. This pin should be connected to the VBUS signal of a USB network. A 5 V signal on this pin indicates a USB network connection.", 9 ~{RST}/C2CK (io), 10 P3.0/C2D (io), 11 P2.7 (io) "Port 2.7.", 12 P2.6 (io) "Port 2.6.", 13 P2.5 (io) "Port 2.5.", 14 P2.4 (io) "Port 2.4.", 15 P2.3 (io) "Port 2.3.", 16 P2.2 (io) "Port 2.2.", 17 P2.1 (io) "Port 2.1.", 18 P2.0 (io) "Port 2.0.", 19 P1.7 (io) "Port 1.7.", 20 P1.6 (io) "Port 1.6.", 21 P1.5 (io) "Port 1.5.", 22 P1.4 (io) "Port 1.4.", 23 P1.3 (io) "Port 1.3.", 24 P1.2 (io) "Port 1.2.", 25 P1.1 (io) "Port 1.1.", 26 P1.0 (io) "Port 1.0.", 27 P0.7 (io) "Port 0.7.", 28 P0.6 (io) "Port 0.6.", 29 P0.5 (io) "Port 0.5.", 30 P0.4 (io) "Port 0.4.", 31 P0.3 (io) "Port 0.3.", 32 P0.2 (io) "Port 0.2.", 33 GND (power)

## C8051F343-GQ
designator U?
Full Speed USB Flash MCU Family, 48 MHz, 2.25 kB RAM, 32 kB Flash, -40 to 85 degC, 32-pin QFP; Manufacturer: Silicon Labs; PartNumber: C8051F343-GQ; ADC 1: 10-bit, 21-ch., 200 ksps; AEC-Q100: FALSE; Comparators: 2; Debug Interface: C2; Dig I/O Pins: 25; Flash: 32 kB; Internal Osc. Accuracy: +/-0.25%; MCU Core: 8051; MHz: 48; PCA Channels: 5; RAM: 2.25 kB; Temp Sensor: TRUE; Timers (16-bit): 4; Sub-Family: USB MCUs
footprint SLAB-LQFP-32_N (QFP, 32-Leads, Body 7x7mm, Pitch 0.8mm, IPC Medium Density)
footprint SLAB-LQFP-32_L (QFP, 32-Leads, Body 7x7mm, Pitch 0.8mm, IPC High Density)
footprint SLAB-LQFP-32_M (QFP, 32-Leads, Body 7x7mm, Pitch 0.8mm, IPC Low Density)
pins: 1 P0.1 (io) "Port 0.1", 2 P0.0 (io) "Port 0.0. See Section 15 for a complete description of Port 0", 3 GND (power) "Ground.", 4 D+ (io) "USB D+.", 5 D- (io) "USB D-.", 6 VDD (power) "2.7-3.6 V Power Supply Voltage Input. 3.3 V Voltage Regulator Output. See Section 8.", 7 REGIN (power) "5 V Regulator Input. This pin is the input to the on-chip voltage regulator.", 8 VBUS (in) "VBUS Sense Input. This pin should be connected to the VBUS signal of a USB network. A 5 V signal on this pin indicates a USB network connection.", 9 ~{RST}/C2CK (io), 10 P3.0/C2D (io), 11 P2.7 (io) "Port 2.7.", 12 P2.6 (io) "Port 2.6.", 13 P2.5 (io) "Port 2.5.", 14 P2.4 (io) "Port 2.4.", 15 P2.3 (io) "Port 2.3.", 16 P2.2 (io) "Port 2.2.", 17 P2.1 (io) "Port 2.1.", 18 P2.0 (io) "Port 2.0. See Section 15 for a complete description of Port 2.", 19 P1.7 (io) "Port 1.7.", 20 P1.6 (io) "Port 1.6.", 21 P1.5 (io) "Port 1.5.", 22 P1.4 (io) "Port 1.4.", 23 P1.3 (io) "Port 1.3.", 24 P1.2 (io) "Port 1.2.", 25 P1.1 (io) "Port 1.1.", 26 P1.0 (io) "Port 1.0. See Section 15 for a complete description of Port 3.", 27 P0.7 (io) "Port 0.7", 28 P0.6 (io) "Port 0.6", 29 P0.5 (io) "Port 0.5", 30 P0.4 (io) "Port 0.4", 31 P0.3 (io) "Port 0.3", 32 P0.2 (io) "Port 0.2"

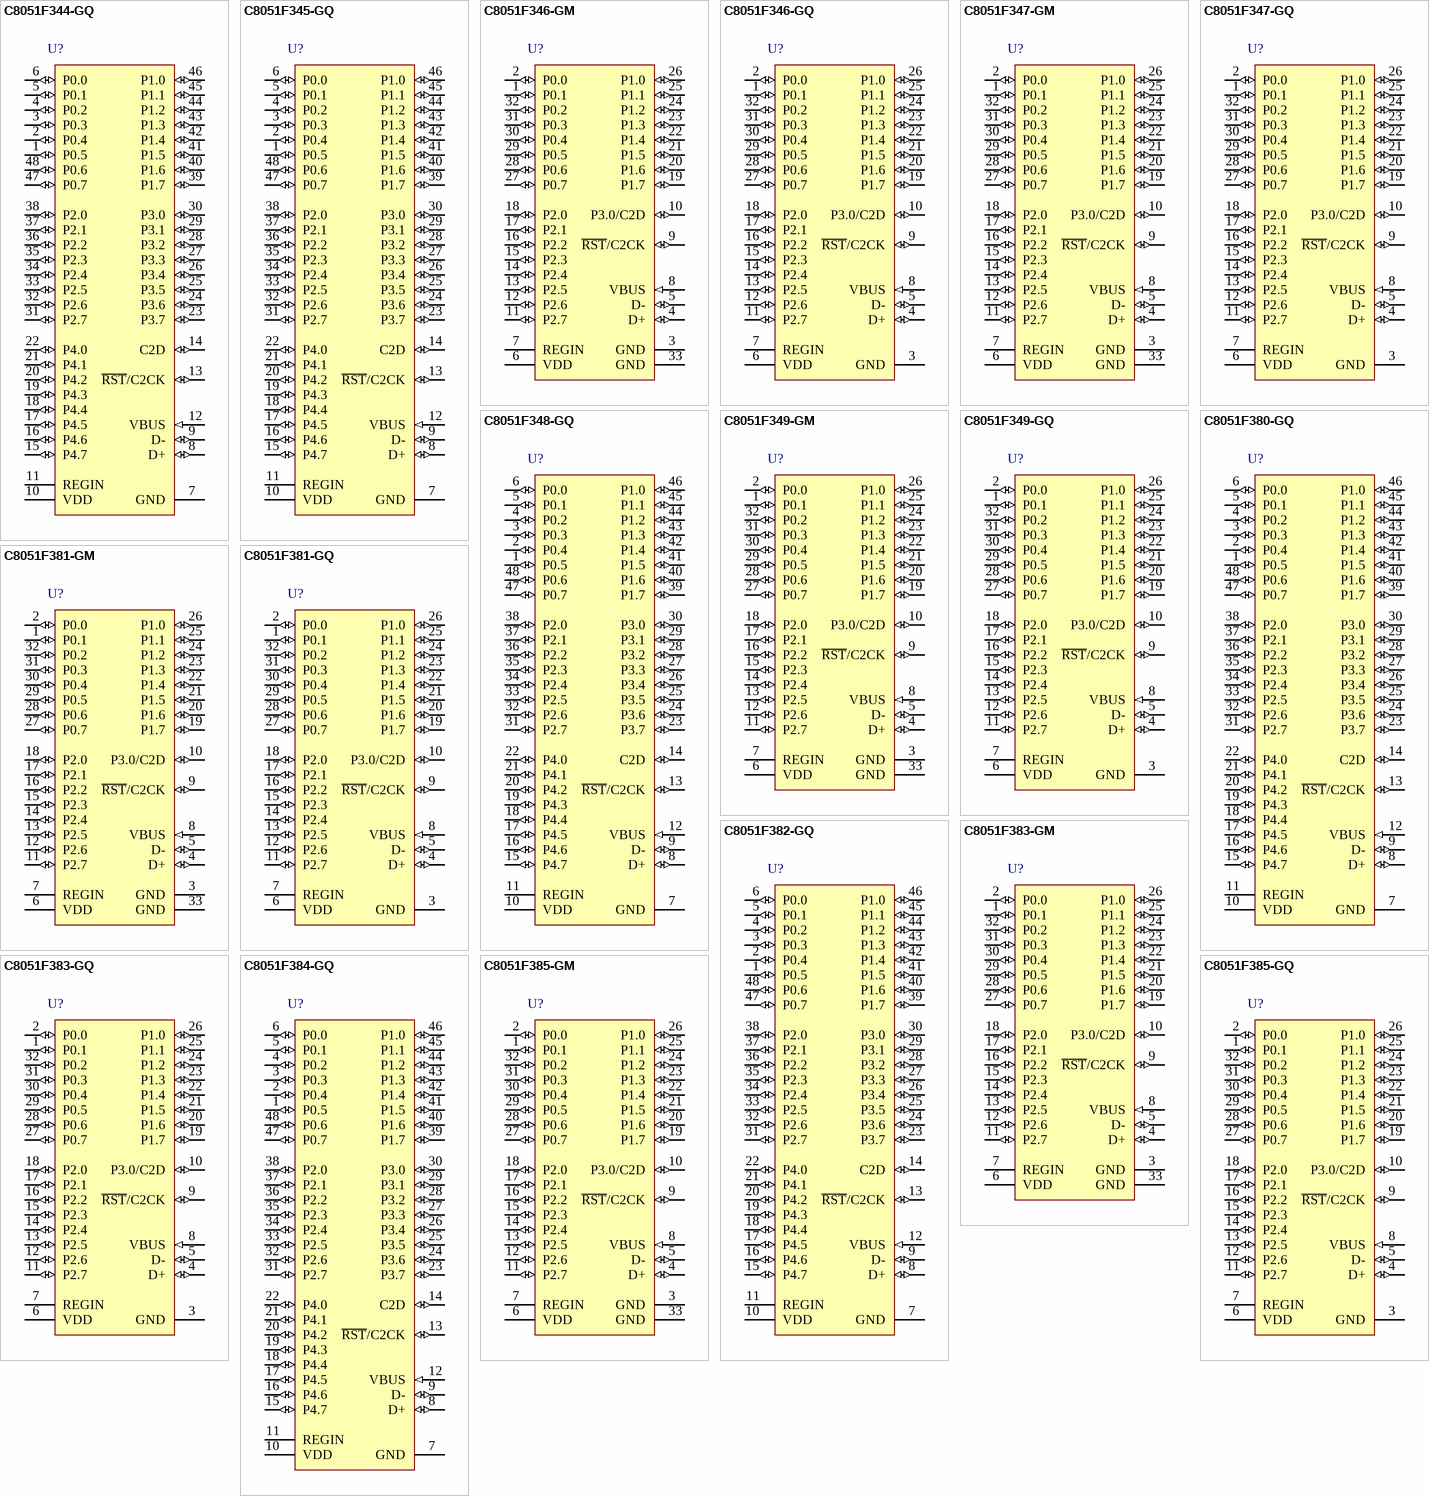
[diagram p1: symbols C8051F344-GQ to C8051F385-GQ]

## C8051F344-GQ
designator U?
Full Speed USB Flash MCU Family, 25 MHz, 4.25 kB RAM, 64 kB Flash, -40 to 85 degC, 48-pin QFP; Manufacturer: Silicon Labs; PartNumber: C8051F344-GQ; ADC 1: 10-bit, 20-ch., 200 ksps; AEC-Q100: FALSE; Comparators: 2; Debug Interface: C2; Dig I/O Pins: 40; Flash: 64 kB; Internal Osc. Accuracy: +/-0.25%; MCU Core: 8051; MHz: 25; PCA Channels: 5; RAM: 4.25 kB; Temp Sensor: TRUE; Timers (16-bit): 4; Sub-Family: USB MCUs
footprint SLAB-TQFP-48_N (QFP, 48-Leads, Body 7x7mm, Pitch 0.5mm, IPC Medium Density)
footprint SLAB-TQFP-48_L (QFP, 48-Leads, Body 7x7mm, Pitch 0.5mm, IPC High Density)
footprint SLAB-TQFP-48_M (QFP, 48-Leads, Body 7x7mm, Pitch 0.5mm, IPC Low Density)
pins: 1 P0.5 (io) "Port 0.5.", 2 P0.4 (io) "Port 0.4.", 3 P0.3 (io) "Port 0.3.", 4 P0.2 (io) "Port 0.2.", 5 P0.1 (io) "Port 0.1", 6 P0.0 (io) "Port 0.0.", 7 GND (power) "Ground.", 8 D+ (io) "USB D+.", 9 D- (io) "USB D-.", 10 VDD (power) "2.7-3.6 V Power Supply Voltage Input. 3.3 V Voltage Regulator Output.", 11 REGIN (power) "5 V Regulator Input. This pin is the input to the on-chip voltage regulator.", 12 VBUS (in) "VBUS Sense Input. This pin should be connected to the VBUS signal of a USB network. A 5 V signal on this pin indicates a USB network connection.", 13 ~{RST}/C2CK (io), 14 C2D (io) "Bi-directional data signal for the C2 Debug Interface.", 15 P4.7 (io) "Port 4.7.", 16 P4.6 (io) "Port 4.6.", 17 P4.5 (io) "Port 4.5.", 18 P4.4 (io) "Port 4.4.", 19 P4.3 (io) "Port 4.3.", 20 P4.2 (io) "Port 4.2.", 21 P4.1 (io) "Port 4.1.", 22 P4.0 (io) "Port 4.0.", 23 P3.7 (io) "Port 3.7.", 24 P3.6 (io) "Port 3.6.", 25 P3.5 (io) "Port 3.5.", 26 P3.4 (io) "Port 3.4.", 27 P3.3 (io) "Port 3.3.", 28 P3.2 (io) "Port 3.2.", 29 P3.1 (io) "Port 3.1.", 30 P3.0 (io) "Port 3.0.", 31 P2.7 (io) "Port 2.7.", 32 P2.6 (io) "Port 2.6.", 33 P2.5 (io) "Port 2.5.", 34 P2.4 (io) "Port 2.4.", 35 P2.3 (io) "Port 2.3.", 36 P2.2 (io) "Port 2.2.", 37 P2.1 (io) "Port 2.1.", 38 P2.0 (io) "Port 2.0.", 39 P1.7 (io) "Port 1.7.", 40 P1.6 (io) "Port 1.6.", 41 P1.5 (io) "Port 1.5.", 42 P1.4 (io) "Port 1.4.", 43 P1.3 (io) "Port 1.3.", 44 P1.2 (io) "Port 1.2.", 45 P1.1 (io) "Port 1.1.", 46 P1.0 (io) "Port 1.0.", 47 P0.7 (io) "Port 0.7.", 48 P0.6 (io) "Port 0.6."

## C8051F345-GQ
designator U?
Full Speed USB Flash MCU Family, 25 MHz, 2.25 kB RAM, 32 kB Flash, -40 to 85 degC, 48-pin QFP; Manufacturer: Silicon Labs; PartNumber: C8051F345-GQ; ADC 1: 10-bit, 20-ch., 200 ksps; AEC-Q100: FALSE; Comparators: 2; Debug Interface: C2; Dig I/O Pins: 40; Flash: 32 kB; Internal Osc. Accuracy: +/-0.25%; MCU Core: 8051; MHz: 25; PCA Channels: 5; RAM: 2.25 kB; Temp Sensor: TRUE; Timers (16-bit): 4; Sub-Family: USB MCUs
footprint SLAB-TQFP-48_N (QFP, 48-Leads, Body 7x7mm, Pitch 0.5mm, IPC Medium Density)
footprint SLAB-TQFP-48_L (QFP, 48-Leads, Body 7x7mm, Pitch 0.5mm, IPC High Density)
footprint SLAB-TQFP-48_M (QFP, 48-Leads, Body 7x7mm, Pitch 0.5mm, IPC Low Density)
pins: 1 P0.5 (io) "Port 0.5.", 2 P0.4 (io) "Port 0.4.", 3 P0.3 (io) "Port 0.3.", 4 P0.2 (io) "Port 0.2.", 5 P0.1 (io) "Port 0.1", 6 P0.0 (io) "Port 0.0.", 7 GND (power) "Ground.", 8 D+ (io) "USB D+.", 9 D- (io) "USB D-.", 10 VDD (power) "2.7-3.6 V Power Supply Voltage Input. 3.3 V Voltage Regulator Output.", 11 REGIN (power) "5 V Regulator Input. This pin is the input to the on-chip voltage regulator.", 12 VBUS (in) "VBUS Sense Input. This pin should be connected to the VBUS signal of a USB network. A 5 V signal on this pin indicates a USB network connection.", 13 ~{RST}/C2CK (io), 14 C2D (io) "Bi-directional data signal for the C2 Debug Interface.", 15 P4.7 (io) "Port 4.7.", 16 P4.6 (io) "Port 4.6.", 17 P4.5 (io) "Port 4.5.", 18 P4.4 (io) "Port 4.4.", 19 P4.3 (io) "Port 4.3.", 20 P4.2 (io) "Port 4.2.", 21 P4.1 (io) "Port 4.1.", 22 P4.0 (io) "Port 4.0.", 23 P3.7 (io) "Port 3.7.", 24 P3.6 (io) "Port 3.6.", 25 P3.5 (io) "Port 3.5.", 26 P3.4 (io) "Port 3.4.", 27 P3.3 (io) "Port 3.3.", 28 P3.2 (io) "Port 3.2.", 29 P3.1 (io) "Port 3.1.", 30 P3.0 (io) "Port 3.0.", 31 P2.7 (io) "Port 2.7.", 32 P2.6 (io) "Port 2.6.", 33 P2.5 (io) "Port 2.5.", 34 P2.4 (io) "Port 2.4.", 35 P2.3 (io) "Port 2.3.", 36 P2.2 (io) "Port 2.2.", 37 P2.1 (io) "Port 2.1.", 38 P2.0 (io) "Port 2.0.", 39 P1.7 (io) "Port 1.7.", 40 P1.6 (io) "Port 1.6.", 41 P1.5 (io) "Port 1.5.", 42 P1.4 (io) "Port 1.4.", 43 P1.3 (io) "Port 1.3.", 44 P1.2 (io) "Port 1.2.", 45 P1.1 (io) "Port 1.1.", 46 P1.0 (io) "Port 1.0.", 47 P0.7 (io) "Port 0.7.", 48 P0.6 (io) "Port 0.6."

## C8051F346-GM
designator U?
Full Speed USB Flash MCU Family, 25 MHz, 4.25 kB RAM, 64 kB Flash, -40 to 85 degC, 32-pin QFN; Manufacturer: Silicon Labs; PartNumber: C8051F346-GM; ADC 1: 10-bit, 21-ch., 200 ksps; AEC-Q100: FALSE; Comparators: 2; Debug Interface: C2; Dig I/O Pins: 25; Flash: 64 kB; Internal Osc. Accuracy: +/-0.25%; MCU Core: 8051; PCA Channels: 5; RAM: 4.25 kB; Temp Sensor: TRUE; Timers (16-bit): 4; Sub-Family: USB MCUs
footprint SLAB-QFN-32-3300x3300TP_N (QFN, 32-Leads, Body 5x5mm, Pitch 0.5mm, Thermal Pad 3.3x3.3mm, IPC Medium Density)
footprint SLAB-QFN-32-3300x3300TP_L (QFN, 32-Leads, Body 5x5mm, Pitch 0.5mm, Thermal Pad 3.3x3.3mm, IPC High Density)
footprint SLAB-QFN-32-3300x3300TP_M (QFN, 32-Leads, Body 5x5mm, Pitch 0.5mm, Thermal Pad 3.3x3.3mm, IPC Low Density)
pins: 1 P0.1 (io) "Port 0.1.", 2 P0.0 (io) "Port 0.0.", 3 GND (power) "Ground.", 4 D+ (io) "USB D+.", 5 D- (io) "USB D-", 6 VDD (power) "2.7-3.6 V Power Supply Voltage Input. 3.3 V Voltage Regulator Output.", 7 REGIN (power) "5 V Regulator Input. This pin is the input to the on-chip  voltage regulator.", 8 VBUS (in) "VBUS Sense Input. This pin should be connected to the VBUS signal of a USB network. A 5 V signal on this pin indicates a USB network connection.", 9 ~{RST}/C2CK (io), 10 P3.0/C2D (io), 11 P2.7 (io) "Port 2.7.", 12 P2.6 (io) "Port 2.6.", 13 P2.5 (io) "Port 2.5.", 14 P2.4 (io) "Port 2.4.", 15 P2.3 (io) "Port 2.3.", 16 P2.2 (io) "Port 2.2.", 17 P2.1 (io) "Port 2.1.", 18 P2.0 (io) "Port 2.0.", 19 P1.7 (io) "Port 1.7.", 20 P1.6 (io) "Port 1.6.", 21 P1.5 (io) "Port 1.5.", 22 P1.4 (io) "Port 1.4.", 23 P1.3 (io) "Port 1.3.", 24 P1.2 (io) "Port 1.2.", 25 P1.1 (io) "Port 1.1.", 26 P1.0 (io) "Port 1.0.", 27 P0.7 (io) "Port 0.7.", 28 P0.6 (io) "Port 0.6.", 29 P0.5 (io) "Port 0.5.", 30 P0.4 (io) "Port 0.4.", 31 P0.3 (io) "Port 0.3.", 32 P0.2 (io) "Port 0.2.", 33 GND (power)

## C8051F346-GQ
designator U?
Full Speed USB Flash MCU Family, 25 MHz, 4.25 kB RAM, 64 kB Flash, -40 to 85 degC, 32-pin QFP; Manufacturer: Silicon Labs; PartNumber: C8051F346-GQ; ADC 1: 10-bit, 21-ch., 200 ksps; AEC-Q100: FALSE; Comparators: 2; Debug Interface: C2; Dig I/O Pins: 25; Flash: 64 kB; Internal Osc. Accuracy: +/-0.25%; MCU Core: 8051; PCA Channels: 5; RAM: 4.25 kB; Temp Sensor: TRUE; Timers (16-bit): 4; Sub-Family: USB MCUs
footprint SLAB-LQFP-32_N (QFP, 32-Leads, Body 7x7mm, Pitch 0.8mm, IPC Medium Density)
footprint SLAB-LQFP-32_L (QFP, 32-Leads, Body 7x7mm, Pitch 0.8mm, IPC High Density)
footprint SLAB-LQFP-32_M (QFP, 32-Leads, Body 7x7mm, Pitch 0.8mm, IPC Low Density)
pins: 1 P0.1 (io) "Port 0.1", 2 P0.0 (io) "Port 0.0. See Section 15 for a complete description of Port 0", 3 GND (power) "Ground.", 4 D+ (io) "USB D+.", 5 D- (io) "USB D-.", 6 VDD (power) "2.7-3.6 V Power Supply Voltage Input. 3.3 V Voltage Regulator Output. See Section 8.", 7 REGIN (power) "5 V Regulator Input. This pin is the input to the on-chip voltage regulator.", 8 VBUS (in) "VBUS Sense Input. This pin should be connected to the VBUS signal of a USB network. A 5 V signal on this pin indicates a USB network connection.", 9 ~{RST}/C2CK (io), 10 P3.0/C2D (io), 11 P2.7 (io) "Port 2.7.", 12 P2.6 (io) "Port 2.6.", 13 P2.5 (io) "Port 2.5.", 14 P2.4 (io) "Port 2.4.", 15 P2.3 (io) "Port 2.3.", 16 P2.2 (io) "Port 2.2.", 17 P2.1 (io) "Port 2.1.", 18 P2.0 (io) "Port 2.0. See Section 15 for a complete description of Port 2.", 19 P1.7 (io) "Port 1.7.", 20 P1.6 (io) "Port 1.6.", 21 P1.5 (io) "Port 1.5.", 22 P1.4 (io) "Port 1.4.", 23 P1.3 (io) "Port 1.3.", 24 P1.2 (io) "Port 1.2.", 25 P1.1 (io) "Port 1.1.", 26 P1.0 (io) "Port 1.0. See Section 15 for a complete description of Port 3.", 27 P0.7 (io) "Port 0.7", 28 P0.6 (io) "Port 0.6", 29 P0.5 (io) "Port 0.5", 30 P0.4 (io) "Port 0.4", 31 P0.3 (io) "Port 0.3", 32 P0.2 (io) "Port 0.2"

## C8051F347-GM
designator U?
Full Speed USB Flash MCU Family, 25 MHz, 2.25 kB RAM, 32 kB Flash, -40 to 85 degC, 32-pin QFN; Manufacturer: Silicon Labs; PartNumber: C8051F347-GM; ADC 1: 10-bit, 21-ch., 200 ksps; AEC-Q100: FALSE; Comparators: 2; Debug Interface: C2; Dig I/O Pins: 25; Flash: 32 kB; Internal Osc. Accuracy: +/-0.25%; MCU Core: 8051; PCA Channels: 5; RAM: 2.25 kB; Temp Sensor: TRUE; Timers (16-bit): 4; Sub-Family: USB MCUs
footprint SLAB-QFN-32-3300x3300TP_N (QFN, 32-Leads, Body 5x5mm, Pitch 0.5mm, Thermal Pad 3.3x3.3mm, IPC Medium Density)
footprint SLAB-QFN-32-3300x3300TP_L (QFN, 32-Leads, Body 5x5mm, Pitch 0.5mm, Thermal Pad 3.3x3.3mm, IPC High Density)
footprint SLAB-QFN-32-3300x3300TP_M (QFN, 32-Leads, Body 5x5mm, Pitch 0.5mm, Thermal Pad 3.3x3.3mm, IPC Low Density)
pins: 1 P0.1 (io) "Port 0.1.", 2 P0.0 (io) "Port 0.0.", 3 GND (power) "Ground.", 4 D+ (io) "USB D+.", 5 D- (io) "USB D-", 6 VDD (power) "2.7-3.6 V Power Supply Voltage Input. 3.3 V Voltage Regulator Output.", 7 REGIN (power) "5 V Regulator Input. This pin is the input to the on-chip  voltage regulator.", 8 VBUS (in) "VBUS Sense Input. This pin should be connected to the VBUS signal of a USB network. A 5 V signal on this pin indicates a USB network connection.", 9 ~{RST}/C2CK (io), 10 P3.0/C2D (io), 11 P2.7 (io) "Port 2.7.", 12 P2.6 (io) "Port 2.6.", 13 P2.5 (io) "Port 2.5.", 14 P2.4 (io) "Port 2.4.", 15 P2.3 (io) "Port 2.3.", 16 P2.2 (io) "Port 2.2.", 17 P2.1 (io) "Port 2.1.", 18 P2.0 (io) "Port 2.0.", 19 P1.7 (io) "Port 1.7.", 20 P1.6 (io) "Port 1.6.", 21 P1.5 (io) "Port 1.5.", 22 P1.4 (io) "Port 1.4.", 23 P1.3 (io) "Port 1.3.", 24 P1.2 (io) "Port 1.2.", 25 P1.1 (io) "Port 1.1.", 26 P1.0 (io) "Port 1.0.", 27 P0.7 (io) "Port 0.7.", 28 P0.6 (io) "Port 0.6.", 29 P0.5 (io) "Port 0.5.", 30 P0.4 (io) "Port 0.4.", 31 P0.3 (io) "Port 0.3.", 32 P0.2 (io) "Port 0.2.", 33 GND (power)

## C8051F347-GQ
designator U?
Full Speed USB Flash MCU Family, 25 MHz, 2.25 kB RAM, 32 kB Flash, -40 to 85 degC, 32-pin QFP; Manufacturer: Silicon Labs; PartNumber: C8051F347-GQ; ADC 1: 10-bit, 21-ch., 200 ksps; AEC-Q100: FALSE; Comparators: 2; Debug Interface: C2; Dig I/O Pins: 25; Flash: 32 kB; Internal Osc. Accuracy: +/-0.25%; MCU Core: 8051; PCA Channels: 5; RAM: 2.25 kB; Temp Sensor: TRUE; Timers (16-bit): 4; Sub-Family: USB MCUs
footprint SLAB-LQFP-32_N (QFP, 32-Leads, Body 7x7mm, Pitch 0.8mm, IPC Medium Density)
footprint SLAB-LQFP-32_L (QFP, 32-Leads, Body 7x7mm, Pitch 0.8mm, IPC High Density)
footprint SLAB-LQFP-32_M (QFP, 32-Leads, Body 7x7mm, Pitch 0.8mm, IPC Low Density)
pins: 1 P0.1 (io) "Port 0.1", 2 P0.0 (io) "Port 0.0. See Section 15 for a complete description of Port 0", 3 GND (power) "Ground.", 4 D+ (io) "USB D+.", 5 D- (io) "USB D-.", 6 VDD (power) "2.7-3.6 V Power Supply Voltage Input. 3.3 V Voltage Regulator Output. See Section 8.", 7 REGIN (power) "5 V Regulator Input. This pin is the input to the on-chip voltage regulator.", 8 VBUS (in) "VBUS Sense Input. This pin should be connected to the VBUS signal of a USB network. A 5 V signal on this pin indicates a USB network connection.", 9 ~{RST}/C2CK (io), 10 P3.0/C2D (io), 11 P2.7 (io) "Port 2.7.", 12 P2.6 (io) "Port 2.6.", 13 P2.5 (io) "Port 2.5.", 14 P2.4 (io) "Port 2.4.", 15 P2.3 (io) "Port 2.3.", 16 P2.2 (io) "Port 2.2.", 17 P2.1 (io) "Port 2.1.", 18 P2.0 (io) "Port 2.0. See Section 15 for a complete description of Port 2.", 19 P1.7 (io) "Port 1.7.", 20 P1.6 (io) "Port 1.6.", 21 P1.5 (io) "Port 1.5.", 22 P1.4 (io) "Port 1.4.", 23 P1.3 (io) "Port 1.3.", 24 P1.2 (io) "Port 1.2.", 25 P1.1 (io) "Port 1.1.", 26 P1.0 (io) "Port 1.0. See Section 15 for a complete description of Port 3.", 27 P0.7 (io) "Port 0.7", 28 P0.6 (io) "Port 0.6", 29 P0.5 (io) "Port 0.5", 30 P0.4 (io) "Port 0.4", 31 P0.3 (io) "Port 0.3", 32 P0.2 (io) "Port 0.2"

## C8051F348-GQ
designator U?
Full Speed USB Flash MCU Family, 25 MHz, 2.25 kB RAM, 32 kB Flash, -40 to 85 degC, 48-pin QFP; Manufacturer: Silicon Labs; PartNumber: C8051F348-GQ; AEC-Q100: FALSE; Comparators: 2; Debug Interface: C2; Dig I/O Pins: 40; Flash: 32 kB; Internal Osc. Accuracy: +/-0.25%; MCU Core: 8051; MHz: 25; PCA Channels: 5; RAM: 2.25 kB; Timers (16-bit): 4; Sub-Family: USB MCUs
footprint SLAB-TQFP-48_N (QFP, 48-Leads, Body 7x7mm, Pitch 0.5mm, IPC Medium Density)
footprint SLAB-TQFP-48_L (QFP, 48-Leads, Body 7x7mm, Pitch 0.5mm, IPC High Density)
footprint SLAB-TQFP-48_M (QFP, 48-Leads, Body 7x7mm, Pitch 0.5mm, IPC Low Density)
pins: 1 P0.5 (io) "Port 0.5.", 2 P0.4 (io) "Port 0.4.", 3 P0.3 (io) "Port 0.3.", 4 P0.2 (io) "Port 0.2.", 5 P0.1 (io) "Port 0.1", 6 P0.0 (io) "Port 0.0.", 7 GND (power) "Ground.", 8 D+ (io) "USB D+.", 9 D- (io) "USB D-.", 10 VDD (power) "2.7-3.6 V Power Supply Voltage Input. 3.3 V Voltage Regulator Output.", 11 REGIN (power) "5 V Regulator Input. This pin is the input to the on-chip voltage regulator.", 12 VBUS (in) "VBUS Sense Input. This pin should be connected to the VBUS signal of a USB network. A 5 V signal on this pin indicates a USB network connection.", 13 ~{RST}/C2CK (io), 14 C2D (io) "Bi-directional data signal for the C2 Debug Interface.", 15 P4.7 (io) "Port 4.7.", 16 P4.6 (io) "Port 4.6.", 17 P4.5 (io) "Port 4.5.", 18 P4.4 (io) "Port 4.4.", 19 P4.3 (io) "Port 4.3.", 20 P4.2 (io) "Port 4.2.", 21 P4.1 (io) "Port 4.1.", 22 P4.0 (io) "Port 4.0.", 23 P3.7 (io) "Port 3.7.", 24 P3.6 (io) "Port 3.6.", 25 P3.5 (io) "Port 3.5.", 26 P3.4 (io) "Port 3.4.", 27 P3.3 (io) "Port 3.3.", 28 P3.2 (io) "Port 3.2.", 29 P3.1 (io) "Port 3.1.", 30 P3.0 (io) "Port 3.0.", 31 P2.7 (io) "Port 2.7.", 32 P2.6 (io) "Port 2.6.", 33 P2.5 (io) "Port 2.5.", 34 P2.4 (io) "Port 2.4.", 35 P2.3 (io) "Port 2.3.", 36 P2.2 (io) "Port 2.2.", 37 P2.1 (io) "Port 2.1.", 38 P2.0 (io) "Port 2.0.", 39 P1.7 (io) "Port 1.7.", 40 P1.6 (io) "Port 1.6.", 41 P1.5 (io) "Port 1.5.", 42 P1.4 (io) "Port 1.4.", 43 P1.3 (io) "Port 1.3.", 44 P1.2 (io) "Port 1.2.", 45 P1.1 (io) "Port 1.1.", 46 P1.0 (io) "Port 1.0.", 47 P0.7 (io) "Port 0.7.", 48 P0.6 (io) "Port 0.6."

## C8051F349-GM
designator U?
Full Speed USB Flash MCU Family, 25 MHz, 2.25 kB RAM, 32 kB Flash, -40 to 85 degC, 32-pin QFN; Manufacturer: Silicon Labs; PartNumber: C8051F349-GM; AEC-Q100: FALSE; Comparators: 2; Debug Interface: C2; Dig I/O Pins: 25; Flash: 32 kB; Internal Osc. Accuracy: +/-0.25%; MCU Core: 8051; PCA Channels: 5; RAM: 2.25 kB; Timers (16-bit): 4; Sub-Family: USB MCUs
footprint SLAB-QFN-32-3300x3300TP_N (QFN, 32-Leads, Body 5x5mm, Pitch 0.5mm, Thermal Pad 3.3x3.3mm, IPC Medium Density)
footprint SLAB-QFN-32-3300x3300TP_L (QFN, 32-Leads, Body 5x5mm, Pitch 0.5mm, Thermal Pad 3.3x3.3mm, IPC High Density)
footprint SLAB-QFN-32-3300x3300TP_M (QFN, 32-Leads, Body 5x5mm, Pitch 0.5mm, Thermal Pad 3.3x3.3mm, IPC Low Density)
pins: 1 P0.1 (io) "Port 0.1.", 2 P0.0 (io) "Port 0.0.", 3 GND (power) "Ground.", 4 D+ (io) "USB D+.", 5 D- (io) "USB D-", 6 VDD (power) "2.7-3.6 V Power Supply Voltage Input. 3.3 V Voltage Regulator Output.", 7 REGIN (power) "5 V Regulator Input. This pin is the input to the on-chip  voltage regulator.", 8 VBUS (in) "VBUS Sense Input. This pin should be connected to the VBUS signal of a USB network. A 5 V signal on this pin indicates a USB network connection.", 9 ~{RST}/C2CK (io), 10 P3.0/C2D (io), 11 P2.7 (io) "Port 2.7.", 12 P2.6 (io) "Port 2.6.", 13 P2.5 (io) "Port 2.5.", 14 P2.4 (io) "Port 2.4.", 15 P2.3 (io) "Port 2.3.", 16 P2.2 (io) "Port 2.2.", 17 P2.1 (io) "Port 2.1.", 18 P2.0 (io) "Port 2.0.", 19 P1.7 (io) "Port 1.7.", 20 P1.6 (io) "Port 1.6.", 21 P1.5 (io) "Port 1.5.", 22 P1.4 (io) "Port 1.4.", 23 P1.3 (io) "Port 1.3.", 24 P1.2 (io) "Port 1.2.", 25 P1.1 (io) "Port 1.1.", 26 P1.0 (io) "Port 1.0.", 27 P0.7 (io) "Port 0.7.", 28 P0.6 (io) "Port 0.6.", 29 P0.5 (io) "Port 0.5.", 30 P0.4 (io) "Port 0.4.", 31 P0.3 (io) "Port 0.3.", 32 P0.2 (io) "Port 0.2.", 33 GND (power)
